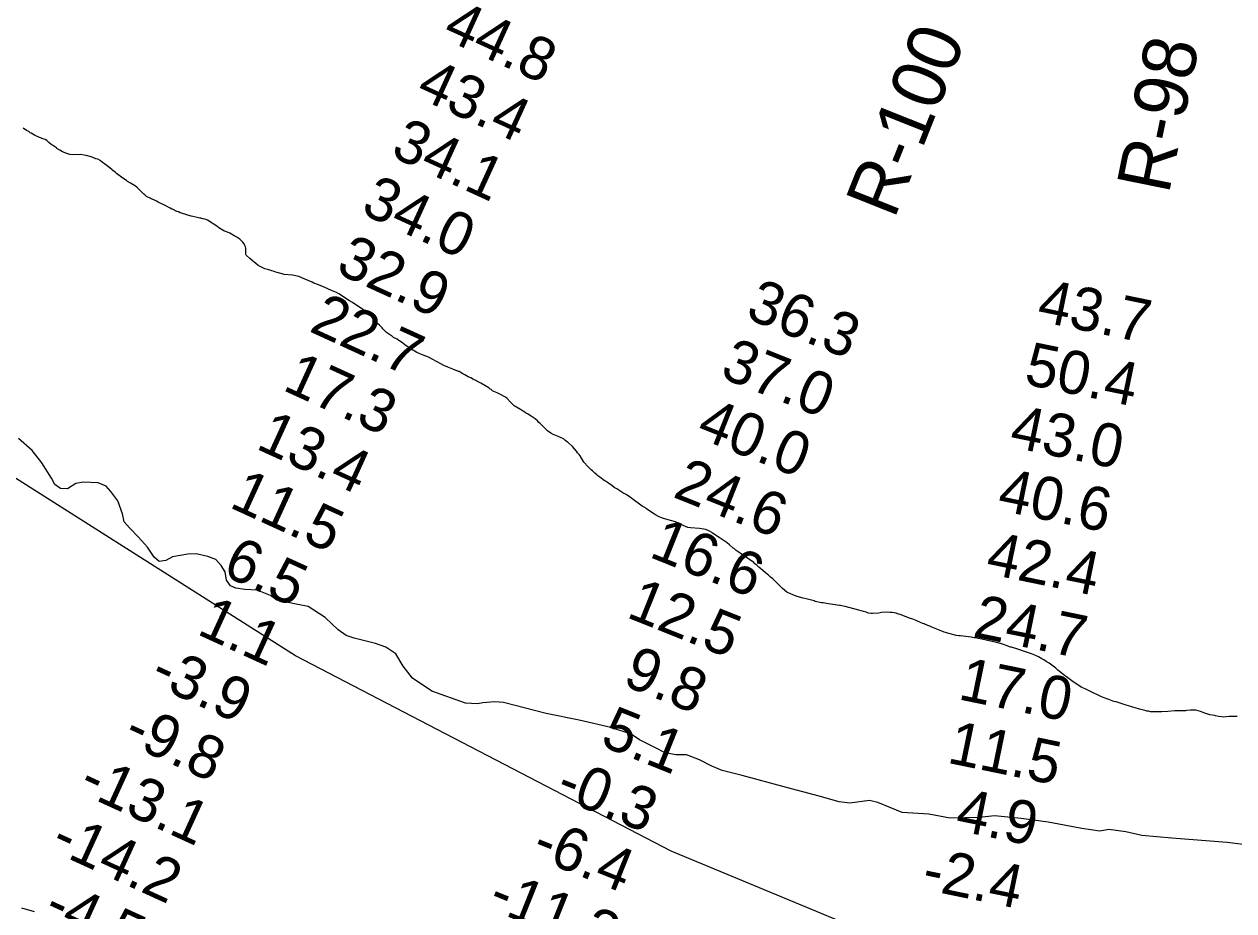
# Model space of a CAD drawing. Extents: x 3146026 to 3183936, y 897894 to 923344.
# Drawn here: x 3158441 to 3160319, y 912037 to 913413 of the extents above; entities that cross this region are included whole.
import ezdxf

# ---------------------------------------------------------------- set-up
doc = ezdxf.new("R2010")
doc.units = 0
for name, color, linetype in [('V-RIVR-EDGE', 7, 'Continuous'), ('V-RIVR-RANG', 7, 'Continuous'), ('V-RIVR-RANG-IDEN', 7, 'Continuous'), ('V-SITE-VEGE', 7, 'Continuous'), ('V-TOPO-BNDY', 7, 'Continuous')]:
    doc.layers.add(name, color=color, linetype=linetype)

msp = doc.modelspace()

# ---------------------------------------------------------------- linework, layer by layer
at = {"layer": 'V-RIVR-EDGE'}
for points in [[(3158881.7, 912509.4), (3158865.3, 912512.4), (3158833, 912518.9), (3158823.3, 912526.2), (3158802.6, 912534.8), (3158783.4, 912535.5), (3158769.1, 912537.7), (3158760.9, 912541.3), (3158754.8, 912550.2), (3158752.7, 912563), (3158746.3, 912572.7), (3158738.4, 912582.5), (3158725.9, 912587.1), (3158707.7, 912591.1), (3158694.6, 912590.5), (3158671.1, 912586.6), (3158660.8, 912580.6), (3158650.1, 912579.4), (3158642.5, 912585.8), (3158631.9, 912601.3), (3158618.2, 912617.2), (3158604.2, 912631.6), (3158595.7, 912640.7), (3158593.3, 912653.2), (3158586.1, 912673.6), (3158575.4, 912688), (3158568.2, 912695.9), (3158555.4, 912701.4), (3158532.8, 912702.4), (3158520.7, 912700.3), (3158507.8, 912692.1), (3158497.2, 912692.4), (3158488.4, 912698.8), (3158482.9, 912708.6), (3158468, 912732.4), (3158453.2, 912751.6), (3158431.6, 912770.3)], [(3160363, 912136), (3160308.5, 912142.8), (3160222.4, 912149.4), (3160175.8, 912153.5), (3160151.1, 912159.6), (3160124.9, 912163.3), (3160110.6, 912160.6), (3160082.9, 912164.7), (3160030.6, 912174.2), (3159988.5, 912180.1), (3159947.4, 912184.2), (3159923.7, 912181.5), (3159878.6, 912180.7), (3159845.4, 912186.9), (3159803.7, 912189.7), (3159786.1, 912196.5), (3159766.3, 912205), (3159752.9, 912208.1), (3159722.7, 912203.9), (3159706, 912205.8), (3159675.2, 912214.7), (3159624.1, 912228.2), (3159555.3, 912246.7), (3159524.6, 912254.7), (3159508.2, 912261.4), (3159489.3, 912271.2), (3159468.9, 912279.2), (3159452.2, 912279.2), (3159436, 912282.3), (3159419.6, 912290.6), (3159396.2, 912302.2), (3159383.1, 912311.1), (3159351.5, 912321.5), (3159302.5, 912332.6), (3159251.3, 912343.1), (3159185, 912360), (3159171.3, 912361.5), (3159152.7, 912359.8), (3159144.5, 912358.3), (3159125.9, 912359.2), (3159073.8, 912377.9), (3159043.4, 912398.1), (3159029.2, 912416.7), (3159017.6, 912435.6), (3159002.1, 912446), (3158986, 912452.1), (3158953.1, 912460.1), (3158940.7, 912464.4), (3158928.2, 912473), (3158907.8, 912492.2), (3158881.7, 912509.4)], [(3158436.6, 912041.7), (3158456.4, 912035.7)]]:
    msp.add_lwpolyline(points, dxfattribs=at)
at = {"layer": 'V-SITE-VEGE'}
for points in [[(3158738.2, 913100.8), (3158733.9, 913103.2), (3158732.6, 913104.3), (3158725.2, 913108.9), (3158721.2, 913110.7), (3158718.2, 913111.2), (3158714.7, 913112.3), (3158713.6, 913112.3), (3158707.4, 913113.9), (3158702.3, 913114.7), (3158699.8, 913115.2), (3158696.6, 913116.3), (3158694.2, 913116.8), (3158693.1, 913117.3), (3158685, 913120), (3158682.8, 913120.5), (3158680.1, 913121.8), (3158677.7, 913122.6), (3158670.9, 913126.4), (3158669.8, 913126.4), (3158667.4, 913128), (3158660.6, 913131.4), (3158648.7, 913137.3), (3158646.3, 913138.4), (3158642.2, 913140.5), (3158637.9, 913142.4), (3158636.2, 913143.4), (3158635.2, 913143.7), (3158632.7, 913145), (3158630.8, 913146.1), (3158628.1, 913148.5), (3158626.5, 913149.6), (3158617, 913159), (3158615.6, 913160.1), (3158611.8, 913162.7), (3158605.6, 913166.5), (3158601.3, 913169.4), (3158599.4, 913170.5), (3158593.7, 913174.5), (3158583.9, 913181.8), (3158582, 913183.6), (3158578.5, 913186), (3158577.4, 913187.1), (3158571.5, 913191.9), (3158567.4, 913194.9), (3158565.5, 913196.5), (3158562.3, 913198.6), (3158558.5, 913201.9), (3158554.9, 913203.7), (3158552, 913204.5), (3158550.1, 913205.6), (3158548.4, 913205.8), (3158546.3, 913206.9), (3158544.9, 913207.2), (3158536.8, 913209.6), (3158533.8, 913210.1), (3158527.9, 913210.9), (3158524.9, 913210.8), (3158520.6, 913211.1), (3158516.8, 913210.8), (3158511.7, 913211.3), (3158506.8, 913212.6), (3158500.3, 913215.3), (3158496, 913217.7), (3158491.4, 913220.4), (3158490.6, 913221.2), (3158484.6, 913225.5), (3158482.5, 913226.8), (3158479.2, 913229.5), (3158475.7, 913232.7), (3158473.2, 913234.3), (3158469.7, 913235.4), (3158467.6, 913236.4), (3158464.6, 913237.5), (3158456.7, 913241.2), (3158451.6, 913244.2), (3158450.2, 913244.7), (3158448.9, 913245.5), (3158447.8, 913246.6), (3158444.3, 913248.2), (3158439.1, 913251.9)], [(3159190.8, 912832.3), (3159187.8, 912834.5), (3159179.4, 912839), (3159177, 912839.8), (3159175.3, 912840.9), (3159169.7, 912843.3), (3159167.8, 912844.4), (3159165.6, 912846), (3159164, 912846.5), (3159162.1, 912848.7), (3159149.9, 912855.9), (3159147.7, 912856.9), (3159144.7, 912858.8), (3159143.4, 912859.3), (3159142, 912860.4), (3159138.5, 912861.7), (3159134.2, 912864.4), (3159130.1, 912866), (3159124.7, 912869), (3159121.7, 912870.3), (3159117.7, 912873), (3159115.8, 912874), (3159115, 912874), (3159106, 912878), (3159098.2, 912880.7), (3159092.2, 912883.6), (3159087.6, 912886.3), (3159068.4, 912896.4), (3159060, 912899.4), (3159050.3, 912903.9), (3159047.9, 912905.2), (3159045.7, 912906.8), (3159044.3, 912907.4), (3159034, 912914.1), (3159029.2, 912917.8), (3159026.5, 912919.7), (3159022.4, 912922.1), (3159019.7, 912924.2), (3159014.3, 912927.2), (3159011.8, 912928.8), (3159011, 912929.6), (3159003.4, 912934.7), (3158997.5, 912940.6), (3158996.6, 912941.9), (3158995.8, 912942.7), (3158992.8, 912945.7), (3158988.5, 912949.4), (3158987.4, 912950.8), (3158986.3, 912951.6), (3158982.2, 912957.2), (3158980.6, 912959.9), (3158974.1, 912965.8), (3158968.1, 912969.3), (3158966.5, 912970.6), (3158950.5, 912981.4), (3158945.7, 912984), (3158929.1, 912995), (3158925.6, 912996.9), (3158917.8, 913000.1), (3158906.7, 913005.1), (3158902.9, 913006.5), (3158896.1, 913009.4), (3158890.2, 913011.5), (3158887.7, 913012.9), (3158881.8, 913015.2), (3158875.6, 913018.2), (3158866.9, 913021.4), (3158857.4, 913023.5), (3158844.5, 913025), (3158841.2, 913025.6), (3158831.5, 913028.2), (3158828.8, 913029.5), (3158825, 913030.6), (3158818.8, 913032.7), (3158814.2, 913033.8), (3158812.3, 913034.8), (3158810.4, 913035.6), (3158809.1, 913035.9), (3158804.2, 913038.6), (3158799.6, 913042.1), (3158797.7, 913043.9), (3158790.9, 913049.6), (3158785.5, 913054.7), (3158784.7, 913055.7), (3158784.6, 913065.7), (3158784.3, 913067.9), (3158783.5, 913069.8), (3158782.1, 913072.2), (3158780.2, 913074.9), (3158775.3, 913079.4), (3158770.7, 913082.7), (3158767.8, 913084.5), (3158759.9, 913089.1), (3158753.7, 913091.5), (3158751.8, 913092), (3158750.7, 913092.8), (3158748.3, 913094.1), (3158743.1, 913097.3), (3158742, 913098.4), (3158740.1, 913099.5), (3158738.2, 913100.8)], [(3159650.3, 912522.3), (3159644.6, 912523.7), (3159639.5, 912525.2), (3159633.3, 912527.9), (3159630.3, 912529), (3159624.9, 912531.6), (3159621.6, 912534.1), (3159617.6, 912537.8), (3159610, 912545.3), (3159608.1, 912546.9), (3159602.9, 912552), (3159599.6, 912554.7), (3159596.4, 912557.7), (3159594.2, 912559.3), (3159581.2, 912570.3), (3159579, 912572.4), (3159578.2, 912573.5), (3159575.2, 912575.6), (3159573.3, 912577.5), (3159563.6, 912584.5), (3159556.5, 912589), (3159552.2, 912592.2), (3159546, 912596.5), (3159544.9, 912597.3), (3159543.5, 912598.7), (3159541.4, 912599.7), (3159535.7, 912604.8), (3159532.4, 912608.3), (3159519.9, 912616.6), (3159509.4, 912623.3), (3159508.3, 912624.4), (3159504.8, 912626.3), (3159498.8, 912628.9), (3159489.4, 912630.5), (3159475.3, 912631.2), (3159471.3, 912632), (3159460.4, 912636.5), (3159452.1, 912640.5), (3159446.4, 912642.4), (3159433.1, 912646.1), (3159429.1, 912647.4), (3159426.6, 912648.5), (3159419.9, 912652), (3159407.1, 912660.8), (3159405.2, 912662.4), (3159400.1, 912665.3), (3159384.1, 912676.9), (3159381.4, 912679), (3159381.4, 912679.3), (3159376, 912682.5), (3159375.2, 912683.3), (3159370.3, 912685.7), (3159366.8, 912687.8), (3159360.8, 912691.9), (3159358.6, 912692.9), (3159356.5, 912694.3), (3159352.4, 912697.5), (3159348.3, 912700.2), (3159346.4, 912701.8), (3159343.2, 912703.9), (3159341.3, 912704.7), (3159334.5, 912710.1), (3159331.5, 912712.2), (3159329.9, 912713.8), (3159326.7, 912716.2), (3159324.2, 912718.9), (3159322.9, 912719.7), (3159321.2, 912721.6), (3159313.4, 912729.4), (3159312.5, 912730.5), (3159310.6, 912732.3), (3159309.8, 912733.4), (3159304.1, 912743.1), (3159302.5, 912745.2), (3159300, 912747.9), (3159298.4, 912750.3), (3159291.9, 912757.6), (3159285.4, 912764), (3159284.3, 912764.6), (3159281.8, 912766.7), (3159279.9, 912767.8), (3159278, 912769.4), (3159268.8, 912773.7), (3159263.4, 912775.8), (3159261.8, 912776.6), (3159258.6, 912778.5), (3159253.1, 912782.2), (3159242, 912793.2), (3159239.6, 912795.1), (3159237.7, 912797.5), (3159234.1, 912800.7), (3159227.6, 912804.8), (3159222, 912808.5), (3159220.9, 912808.8), (3159219, 912809.8), (3159216.3, 912812), (3159214.4, 912813), (3159211.4, 912815.2), (3159201.6, 912821.1), (3159195.1, 912827.2), (3159190.8, 912832.3)], [(3160259.7, 912348.1), (3160251.3, 912348.1), (3160245.4, 912347.8), (3160244, 912347.2), (3160227.3, 912347.1), (3160216.2, 912346.5), (3160207.1, 912345.7), (3160191.4, 912345.6), (3160189.5, 912345.8), (3160186.3, 912346.6), (3160183.6, 912346.9), (3160182.5, 912347.4), (3160172.5, 912350.1), (3160165.4, 912352.2), (3160162.2, 912353), (3160159, 912354), (3160151.7, 912355.9), (3160145.2, 912358.3), (3160136, 912361.2), (3160132.5, 912361.7), (3160124.9, 912364.9), (3160116, 912368.1), (3160111.1, 912370.2), (3160096.2, 912377.4), (3160087.8, 912381.7), (3160082.9, 912383.6), (3160078.9, 912386), (3160067.2, 912394), (3160059.1, 912400.2), (3160057.5, 912401), (3160048.3, 912408.2), (3160045.5, 912410.6), (3160042.6, 912413.6), (3160032.3, 912421.1), (3160027.4, 912423.8), (3160023.6, 912426.4), (3160020.9, 912428), (3160018.2, 912429.4), (3160015.5, 912431), (3160009.8, 912433.6), (3160004.6, 912435.8), (3159992.2, 912439.8), (3159984.9, 912442.4), (3159973.5, 912446.1), (3159971.9, 912446.4), (3159965.2, 912448.5), (3159962.7, 912449.6), (3159958.1, 912451.2), (3159952.5, 912452.8), (3159927.3, 912458.8), (3159921.6, 912459.6), (3159920, 912460.1), (3159917.6, 912460.4), (3159915.4, 912460.9), (3159913.3, 912461.2), (3159910.8, 912461.7), (3159894.4, 912463.8), (3159891.9, 912463.8), (3159887.6, 912464.3), (3159886.3, 912464.8), (3159878.2, 912466.9), (3159869, 912469.6), (3159865.2, 912470.9), (3159852.7, 912476), (3159849.8, 912477.3), (3159846.8, 912478.9), (3159839.5, 912481.6), (3159837.8, 912482.4), (3159836, 912482.9), (3159833.2, 912484.2), (3159825.4, 912487.4), (3159820.3, 912489.8), (3159815.4, 912491.4), (3159800.8, 912497), (3159798.4, 912497.5), (3159794.3, 912498.8), (3159788.4, 912500.2), (3159785.1, 912500.1), (3159780, 912500.7), (3159771.6, 912499.8), (3159767.8, 912499.2), (3159757.9, 912498.6), (3159755.7, 912498.6), (3159751.4, 912499.1), (3159747.9, 912500.5), (3159743.8, 912501.5), (3159736.8, 912503.7), (3159715.4, 912509.2), (3159712.4, 912509.7), (3159708.1, 912510.8), (3159706.5, 912511), (3159702.7, 912511.3), (3159693, 912512.9), (3159689.2, 912513.6), (3159681.4, 912514.9), (3159678.7, 912515.2), (3159669, 912517.3), (3159667.1, 912518.1), (3159665.4, 912518.4), (3159654.6, 912521), (3159650.3, 912522.3)], [(3160324.2, 912338.5), (3160311.8, 912338.4), (3160302.4, 912337.6), (3160300.2, 912338.1), (3160294.8, 912338.6), (3160290.5, 912339.4), (3160289.4, 912339.9), (3160281.6, 912341), (3160278.6, 912342.3), (3160274, 912343.6), (3160267, 912346.3), (3160259.7, 912348.1)]]:
    msp.add_lwpolyline(points, dxfattribs=at)
at = {"layer": 'V-TOPO-BNDY'}
msp.add_lwpolyline([(3162288, 912035.1), (3162225.5, 912006.3), (3162087.3, 911943.2), (3161778.1, 911799.8), (3161261.5, 911668.3), (3160960.6, 911648.5), (3160815.9, 911663.3), (3160685.6, 911676.6), (3160605.9, 911700), (3160140.6, 911840.9), (3159445.2, 912129.3), (3158861.9, 912432.7), (3158245.4, 912823.6), (3157767.9, 913092.7), (3157135.3, 913454.6), (3156545.8, 913785.7)], dxfattribs=at)

# ---------------------------------------------------------------- texts
at = {"layer": 'V-RIVR-RANG'}
for s, rotation, p in [('44.8', 335.4383, (3159088, 913392.5)), ('43.4', 335.4383, (3159046.7, 913301.5)), ('34.1', 335.4383, (3159007.5, 913209.4)), ('34.0', 335.4383, (3158961.3, 913120.6)), ('32.9', 335.4383, (3158922.4, 913028.4)), ('36.3', 338.1683, (3159558.6, 912957.9)), ('43.7', 348.3783, (3160011.2, 912953)), ('22.7', 335.4383, (3158881.3, 912937.3)), ('37.0', 338.1683, (3159518.9, 912866.1)), ('50.4', 348.3783, (3159991.3, 912855)), ('17.3', 335.4383, (3158840, 912846.2)), ('40.0', 338.1683, (3159482, 912773.2)), ('13.4', 335.4383, (3158798.6, 912755.2)), ('43.0', 348.3783, (3159968.6, 912757.6)), ('24.6', 338.1683, (3159446, 912679.9)), ('11.5', 335.4383, (3158757.3, 912664.1)), ('40.6', 348.3783, (3159949.8, 912659.4)), ('16.6', 338.1683, (3159409.1, 912586.9)), ('6.5', 335.4383, (3158746.2, 912559.2)), ('42.4', 348.3783, (3159931.7, 912561)), ('12.5', 338.1683, (3159373.8, 912493.3)), ('24.7', 348.3783, (3159911.8, 912463)), ('1.1', 335.4383, (3158707, 912467.2)), ('9.8', 338.1683, (3159367.7, 912388.1)), ('-3.9', 335.4383, (3158633, 912391)), ('17.0', 348.3783, (3159889, 912365.6)), ('5.1', 338.1683, (3159333, 912294.3)), ('-9.8', 335.4383, (3158591.9, 912299.9)), ('11.5', 348.3783, (3159872, 912267)), ('-13.1', 335.4383, (3158522.5, 912221.7)), ('-0.3', 338.1683, (3159263, 912214.6)), ('4.9', 348.3783, (3159884.4, 912162.4)), ('-14.2', 335.4383, (3158479, 912131.6)), ('-6.4', 338.1683, (3159226, 912121.7)), ('-2.4', 348.3783, (3159832.2, 912071)), ('-11.2', 338.1683, (3159158.2, 912041.1)), ('-4.5', 335.4383, (3158467.9, 912026.7))]:
    msp.add_text(s, height=67, rotation=rotation, dxfattribs=at).set_placement(p)
at = {"layer": 'V-RIVR-RANG-IDEN'}
for s, rotation, p in [('R-100', 68.3122, (3159791.4, 913109.3)), ('R-98', 78.5245, (3160217.7, 913147.8))]:
    msp.add_text(s, height=83, rotation=rotation, dxfattribs=at).set_placement(p)

doc.saveas('drawing.dxf')
